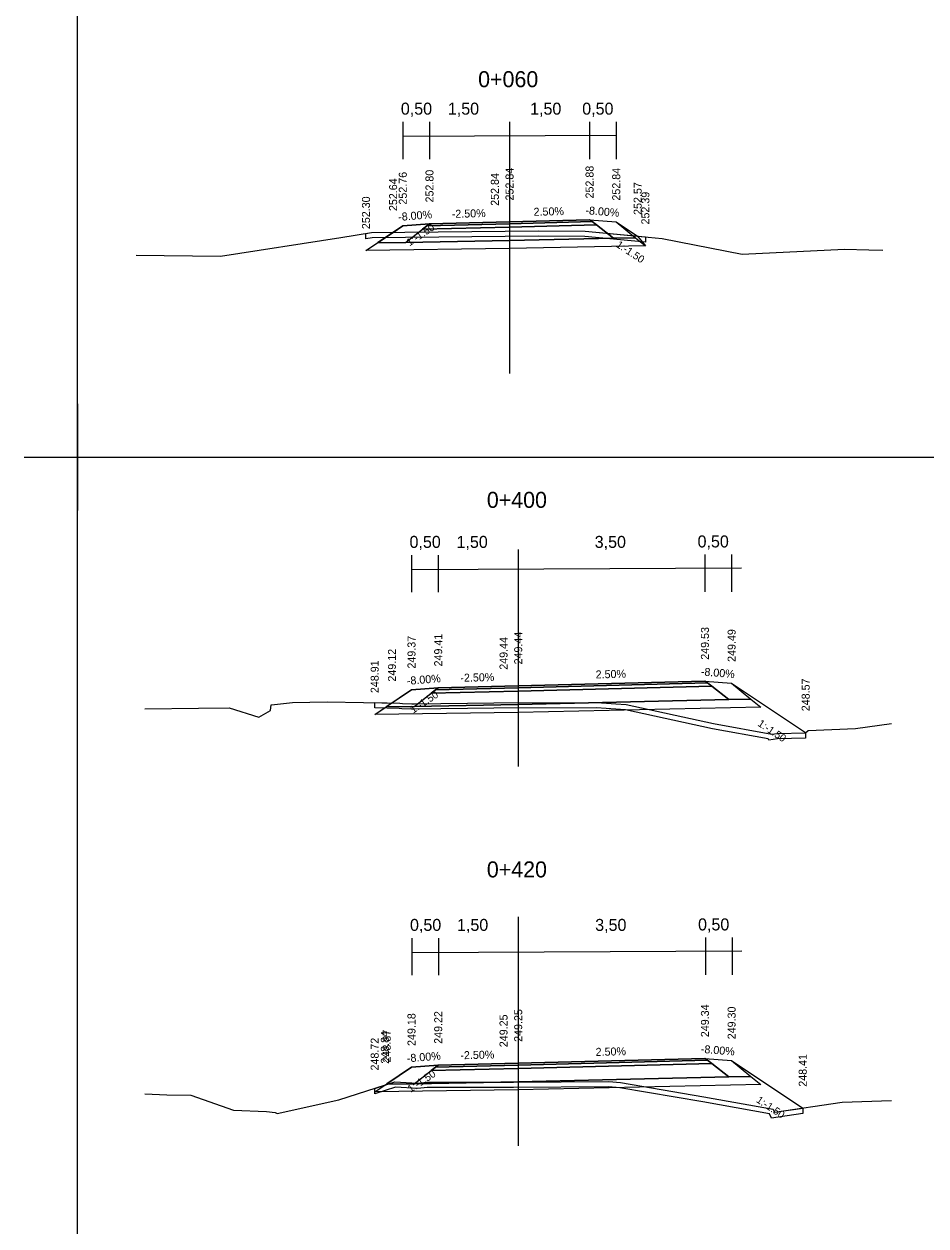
# Model space of a CAD drawing. Extents: x -552501 to -552394, y -1029983 to -1029892.
# Drawn here: x -552500.76 to -552483.85, y -1029937.46 to -1029914.93 of the extents above; entities that cross this region are included whole.
import ezdxf

# ---------------------------------------------------------------- set-up
doc = ezdxf.new("R2010")
doc.units = 0
for name, color, linetype in [('1', 7, 'Continuous'), ('16', 7, 'Continuous'), ('60', 7, 'Continuous'), ('9', 7, 'Continuous'), ('FORMATY', 7, 'Continuous'), ('Implicitní', 7, 'Continuous'), ('rámeček', 7, 'Continuous')]:
    doc.layers.add(name, color=color, linetype=linetype)

msp = doc.modelspace()

# ---------------------------------------------------------------- linework, layer by layer
for points in [[(-552494.346, -1029919.177), (-552493.838, -1029918.838), (-552493.656, -1029918.717), (-552493.156, -1029918.677), (-552491.656, -1029918.64), (-552490.156, -1029918.602), (-552489.656, -1029918.642), (-552489.254, -1029918.91), (-552489.11, -1029919.09)], [(-552498.656, -1029919.262), (-552497.071, -1029919.282), (-552494.815, -1029918.933), (-552494.241, -1029918.843), (-552491.11, -1029918.809), (-552490.237, -1029918.814), (-552488.794, -1029918.955), (-552487.294, -1029919.244), (-552485.378, -1029919.155), (-552484.918, -1029919.167), (-552484.656, -1029919.173)], [(-552494.183, -1029927.875), (-552493.859, -1029927.659), (-552493.493, -1029927.415), (-552492.993, -1029927.375), (-552491.493, -1029927.337), (-552487.993, -1029927.25), (-552487.493, -1029927.29), (-552486.105, -1029928.215)], [(-552498.493, -1029927.771), (-552497.484, -1029927.756), (-552496.91, -1029927.751), (-552496.352, -1029927.926), (-552496.136, -1029927.801), (-552496.124, -1029927.693), (-552496.117, -1029927.694), (-552495.723, -1029927.651), (-552495.076, -1029927.64), (-552493.71, -1029927.661), (-552493.663, -1029927.672), (-552493.488, -1029927.678), (-552493.439, -1029927.678), (-552491.947, -1029927.66), (-552490.022, -1029927.651), (-552489.66, -1029927.678), (-552489.472, -1029927.686), (-552487.83, -1029928.047), (-552486.738, -1029928.242), (-552486.736, -1029928.247), (-552486.642, -1029928.232), (-552486.107, -1029928.217), (-552486.056, -1029928.175), (-552485.168, -1029928.139), (-552484.493, -1029928.042)], [(-552494.183, -1029934.95), (-552493.992, -1029934.823), (-552493.958, -1029934.8), (-552493.493, -1029934.49), (-552492.993, -1029934.45), (-552491.493, -1029934.413), (-552487.993, -1029934.325), (-552487.493, -1029934.365), (-552486.16, -1029935.254)], [(-552498.493, -1029934.988), (-552498.076, -1029935.008), (-552497.628, -1029935.014), (-552496.83, -1029935.293), (-552496.214, -1029935.317), (-552496.051, -1029935.337), (-552496.01, -1029935.354), (-552494.855, -1029935.103), (-552493.804, -1029934.762), (-552493.378, -1029934.787), (-552493.205, -1029934.766), (-552491.583, -1029934.768), (-552489.796, -1029934.754), (-552489.577, -1029934.775), (-552488.016, -1029935.041), (-552486.714, -1029935.274), (-552486.686, -1029935.334), (-552485.421, -1029935.142), (-552484.493, -1029935.115)]]:
    msp.add_lwpolyline(points)
for points in [[(-552491.656, -1029918.68), (-552493.207, -1029918.717), (-552493.284, -1029918.777), (-552491.656, -1029918.74), (-552490.028, -1029918.696), (-552490.105, -1029918.636), (-552491.656, -1029918.68), (-552490.105, -1029918.636), (-552490.156, -1029918.602), (-552491.656, -1029918.64), (-552493.156, -1029918.677), (-552493.207, -1029918.717)], [(-552490.156, -1029918.602), (-552489.656, -1029918.642), (-552489.295, -1029918.94), (-552489.706, -1029918.946), (-552490.028, -1029918.696), (-552490.105, -1029918.636)], [(-552494.346, -1029918.859), (-552494.241, -1029918.843), (-552491.11, -1029918.809), (-552490.237, -1029918.814), (-552489.11, -1029918.924), (-552489.11, -1029919.024), (-552490.243, -1029918.914), (-552491.11, -1029918.909), (-552494.233, -1029918.943), (-552494.346, -1029918.961)], [(-552493.156, -1029918.677), (-552493.656, -1029918.717), (-552494.121, -1029919.027), (-552493.606, -1029919.027)], [(-552493.606, -1029919.027), (-552493.284, -1029918.777), (-552491.656, -1029918.74), (-552490.028, -1029918.696), (-552489.706, -1029918.946), (-552491.656, -1029918.99)], [(-552493.284, -1029918.777), (-552493.207, -1029918.717), (-552491.656, -1029918.68), (-552490.105, -1029918.636), (-552490.028, -1029918.696), (-552491.656, -1029918.74)], [(-552494.346, -1029919.177), (-552494.121, -1029919.027), (-552493.606, -1029919.027), (-552491.656, -1029918.99), (-552489.706, -1029918.946), (-552489.295, -1029918.94), (-552489.11, -1029919.09), (-552491.656, -1029919.14)], [(-552492.993, -1029927.375), (-552493.493, -1029927.415), (-552493.958, -1029927.725), (-552493.444, -1029927.725)], [(-552493.444, -1029927.725), (-552493.122, -1029927.475), (-552491.494, -1029927.437), (-552487.865, -1029927.344), (-552487.543, -1029927.594), (-552491.494, -1029927.687)], [(-552491.494, -1029927.377), (-552493.044, -1029927.415), (-552493.122, -1029927.475), (-552491.494, -1029927.437), (-552487.865, -1029927.344), (-552487.942, -1029927.284), (-552491.494, -1029927.377), (-552487.942, -1029927.284), (-552487.993, -1029927.25), (-552491.493, -1029927.337), (-552492.993, -1029927.375), (-552493.044, -1029927.415)], [(-552493.122, -1029927.475), (-552493.044, -1029927.415), (-552491.494, -1029927.377), (-552487.942, -1029927.284), (-552487.865, -1029927.344), (-552491.494, -1029927.437)], [(-552487.993, -1029927.25), (-552487.493, -1029927.29), (-552487.132, -1029927.587), (-552487.543, -1029927.594), (-552487.865, -1029927.344), (-552487.942, -1029927.284)], [(-552494.183, -1029927.875), (-552493.958, -1029927.725), (-552493.444, -1029927.725), (-552491.494, -1029927.687), (-552487.543, -1029927.594), (-552487.132, -1029927.587), (-552486.947, -1029927.737), (-552491.494, -1029927.837)], [(-552494.183, -1029927.654), (-552493.71, -1029927.661), (-552493.663, -1029927.672), (-552493.488, -1029927.678), (-552493.439, -1029927.678), (-552491.947, -1029927.66), (-552490.022, -1029927.651), (-552489.66, -1029927.678), (-552489.472, -1029927.686), (-552487.83, -1029928.047), (-552486.738, -1029928.242), (-552486.736, -1029928.247), (-552486.642, -1029928.232), (-552486.107, -1029928.217), (-552486.105, -1029928.215), (-552486.105, -1029928.317), (-552486.633, -1029928.332), (-552486.795, -1029928.357), (-552486.807, -1029928.331), (-552487.849, -1029928.145), (-552489.485, -1029927.786), (-552489.666, -1029927.778), (-552490.026, -1029927.751), (-552491.947, -1029927.76), (-552493.438, -1029927.778), (-552493.49, -1029927.778), (-552493.677, -1029927.772), (-552493.723, -1029927.761), (-552494.183, -1029927.754)], [(-552491.494, -1029934.453), (-552493.044, -1029934.49), (-552493.122, -1029934.55), (-552491.494, -1029934.513), (-552487.865, -1029934.419), (-552487.942, -1029934.359), (-552491.494, -1029934.453), (-552487.942, -1029934.359), (-552487.993, -1029934.325), (-552491.493, -1029934.413), (-552492.993, -1029934.45), (-552493.044, -1029934.49)], [(-552493.122, -1029934.55), (-552493.044, -1029934.49), (-552491.494, -1029934.453), (-552487.942, -1029934.359), (-552487.865, -1029934.419), (-552491.494, -1029934.513)], [(-552487.993, -1029934.325), (-552487.493, -1029934.365), (-552487.132, -1029934.663), (-552487.543, -1029934.669), (-552487.865, -1029934.419), (-552487.942, -1029934.359)], [(-552492.993, -1029934.45), (-552493.493, -1029934.49), (-552493.958, -1029934.8), (-552493.444, -1029934.8)], [(-552493.444, -1029934.8), (-552493.122, -1029934.55), (-552491.494, -1029934.513), (-552487.865, -1029934.419), (-552487.543, -1029934.669), (-552491.494, -1029934.763)], [(-552494.183, -1029934.95), (-552493.958, -1029934.8), (-552493.444, -1029934.8), (-552491.494, -1029934.763), (-552487.543, -1029934.669), (-552487.132, -1029934.663), (-552486.947, -1029934.813), (-552491.494, -1029934.913)], [(-552494.183, -1029934.885), (-552493.804, -1029934.762), (-552493.378, -1029934.787), (-552493.205, -1029934.766), (-552491.583, -1029934.768), (-552489.796, -1029934.754), (-552489.577, -1029934.775), (-552488.016, -1029935.041), (-552486.714, -1029935.274), (-552486.686, -1029935.334), (-552486.16, -1029935.254), (-552486.16, -1029935.355), (-552486.746, -1029935.444), (-552486.783, -1029935.363), (-552488.034, -1029935.139), (-552489.59, -1029934.874), (-552489.8, -1029934.854), (-552491.582, -1029934.868), (-552493.199, -1029934.866), (-552493.375, -1029934.888), (-552493.791, -1029934.863), (-552494.183, -1029934.99)]]:
    msp.add_lwpolyline(points, close=True)
at = {"layer": '60'}
for p, q in [((-552491.656, -1029917.481), (-552491.656, -1029921.481)), ((-552491.493, -1029924.78), (-552491.493, -1029928.85)), ((-552491.493, -1029931.667), (-552491.493, -1029935.96))]:
    msp.add_line(p, q, dxfattribs=at)
at = {"layer": '9'}
for p, q in [((-552493.656, -1029916.766), (-552493.656, -1029917.464)), ((-552493.156, -1029916.766), (-552493.156, -1029917.464)), ((-552491.656, -1029916.766), (-552491.656, -1029918.266)), ((-552490.156, -1029916.766), (-552490.156, -1029917.464)), ((-552489.656, -1029916.766), (-552489.656, -1029917.464)), ((-552493.493, -1029924.888), (-552493.493, -1029925.585)), ((-552492.993, -1029924.888), (-552492.993, -1029925.585)), ((-552491.493, -1029924.888), (-552491.493, -1029926.388)), ((-552487.993, -1029924.879), (-552487.993, -1029925.576)), ((-552487.493, -1029924.879), (-552487.493, -1029925.576)), ((-552493.484, -1029932.068), (-552493.484, -1029932.765)), ((-552492.984, -1029932.068), (-552492.984, -1029932.765)), ((-552491.493, -1029932.076), (-552491.493, -1029933.576)), ((-552487.984, -1029932.059), (-552487.984, -1029932.756)), ((-552487.484, -1029932.059), (-552487.484, -1029932.756))]:
    msp.add_line(p, q, dxfattribs=at)
at = {"layer": 'FORMATY'}
for p, q in [((-552499.755, -1029922.05), (-552499.755, -1029924.05)), ((-552500.755, -1029923.05), (-552498.755, -1029923.05))]:
    msp.add_line(p, q, dxfattribs=at)
at = {"layer": 'Implicitní'}
for p, q in [((-552493.646, -1029917.034), (-552489.656, -1029917.016)), ((-552493.483, -1029925.155), (-552487.308, -1029925.128)), ((-552493.474, -1029932.335), (-552487.299, -1029932.308))]:
    msp.add_line(p, q, dxfattribs=at)
at = {"layer": 'rámeček'}
for p, q in [((-552499.755, -1029923.05), (-552499.755, -1029893.35)), ((-552499.755, -1029922.55), (-552499.755, -1029923.05)), ((-552499.755, -1029923.05), (-552394.755, -1029923.05)), ((-552499.755, -1029923.05), (-552394.755, -1029923.05)), ((-552499.755, -1029923.05), (-552394.755, -1029923.05)), ((-552499.755, -1029952.75), (-552499.755, -1029923.05))]:
    msp.add_line(p, q, dxfattribs=at)

# ---------------------------------------------------------------- texts
for rotation, p in [(33.6902, (-552493.53, -1029919.102)), (326.3098, (-552489.671, -1029919.1)), (33.6902, (-552493.46, -1029927.861)), (326.3098, (-552487.016, -1029928.077)), (33.6902, (-552493.509, -1029934.97)), (326.3098, (-552487.043, -1029935.134))]:
    msp.add_text('1:-1.50', height=0.14, rotation=rotation).set_placement(p)
at = {"layer": '1'}
for s, p in [('0+060', (-552492.244, -1029916.116)), ('0+400', (-552492.081, -1029924.002)), ('0+420', (-552492.081, -1029930.93))]:
    msp.add_text(s, height=0.3, dxfattribs=at).set_placement(p)
at = {"layer": '16'}
for s, p in [('0,50', (-552493.693, -1029916.631)), ('1,50', (-552492.812, -1029916.631)), ('1,50', (-552491.27, -1029916.631)), ('0,50', (-552490.293, -1029916.631)), ('0,50', (-552493.53, -1029924.753)), ('1,50', (-552492.649, -1029924.753)), ('3,50', (-552490.059, -1029924.753)), ('0,50', (-552488.131, -1029924.744)), ('0,50', (-552493.521, -1029931.933)), ('1,50', (-552492.64, -1029931.933)), ('3,50', (-552490.05, -1029931.933)), ('0,50', (-552488.122, -1029931.924))]:
    msp.add_text(s, height=0.225, dxfattribs=at).set_placement(p)
for s, rotation, p in [('252.76', 90, (-552493.581, -1029918.317)), ('252.80', 90, (-552493.081, -1029918.277)), ('252.84', 90, (-552491.581, -1029918.24)), ('252.88', 90, (-552490.081, -1029918.202)), ('252.84', 90, (-552489.581, -1029918.242)), ('252.64', 90, (-552493.763, -1029918.438)), ('252.84', 90, (-552491.856, -1029918.34)), ('252.57', 90, (-552489.179, -1029918.51)), ('252.39', 90, (-552489.035, -1029918.69)), ('252.30', 90, (-552494.271, -1029918.777)), ('2.50%', 1.4321, (-552491.203, -1029918.528)), ('-8.00%', 355.4261, (-552490.237, -1029918.496)), ('-8.00%', 4.5739, (-552493.737, -1029918.624)), ('-2.50%', 1.4321, (-552492.737, -1029918.567)), ('249.53', 90, (-552487.918, -1029926.85)), ('249.37', 90, (-552493.418, -1029927.015)), ('249.41', 90, (-552492.918, -1029926.975)), ('249.44', 90, (-552491.693, -1029927.037)), ('249.44', 90, (-552491.418, -1029926.937)), ('249.49', 90, (-552487.418, -1029926.89)), ('249.12', 90, (-552493.784, -1029927.259)), ('248.91', 90, (-552494.108, -1029927.475)), ('-8.00%', 4.5739, (-552493.574, -1029927.321)), ('-2.50%', 1.4321, (-552492.575, -1029927.264)), ('2.50%', 1.4321, (-552490.04, -1029927.201)), ('-8.00%', 355.4261, (-552488.074, -1029927.143)), ('248.57', 90, (-552486.03, -1029927.815)), ('249.22', 90, (-552492.918, -1029934.05)), ('249.25', 90, (-552491.418, -1029934.013)), ('249.34', 90, (-552487.918, -1029933.925)), ('249.30', 90, (-552487.418, -1029933.965)), ('249.18', 90, (-552493.418, -1029934.09)), ('249.25', 90, (-552491.693, -1029934.113)), ('248.84', 90, (-552493.917, -1029934.423)), ('248.87', 90, (-552493.883, -1029934.4)), ('248.72', 90, (-552494.108, -1029934.55)), ('2.50%', 1.4321, (-552490.04, -1029934.277)), ('-8.00%', 355.4261, (-552488.074, -1029934.219)), ('-8.00%', 4.5739, (-552493.574, -1029934.397)), ('-2.50%', 1.4321, (-552492.575, -1029934.34)), ('248.41', 90, (-552486.085, -1029934.854))]:
    msp.add_text(s, height=0.15, rotation=rotation, dxfattribs=at).set_placement(p)

doc.saveas('drawing.dxf')
